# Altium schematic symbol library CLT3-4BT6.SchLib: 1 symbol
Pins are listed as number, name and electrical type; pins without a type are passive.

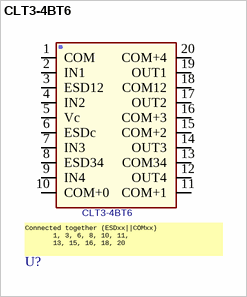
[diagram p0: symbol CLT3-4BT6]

## CLT3-4BT6
designator U?
footprint ST_TSSOP-20
pins: 1 COM, 2 IN1, 3 ESD12, 4 IN2, 5 Vc, 6 ESDc, 7 IN3, 8 ESD34, 9 IN4, 10 COM+0, 11 COM+1, 12 OUT4, 13 COM34, 14 OUT3, 15 COM+2, 16 COM+3, 17 OUT2, 18 COM12, 19 OUT1, 20 COM+4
